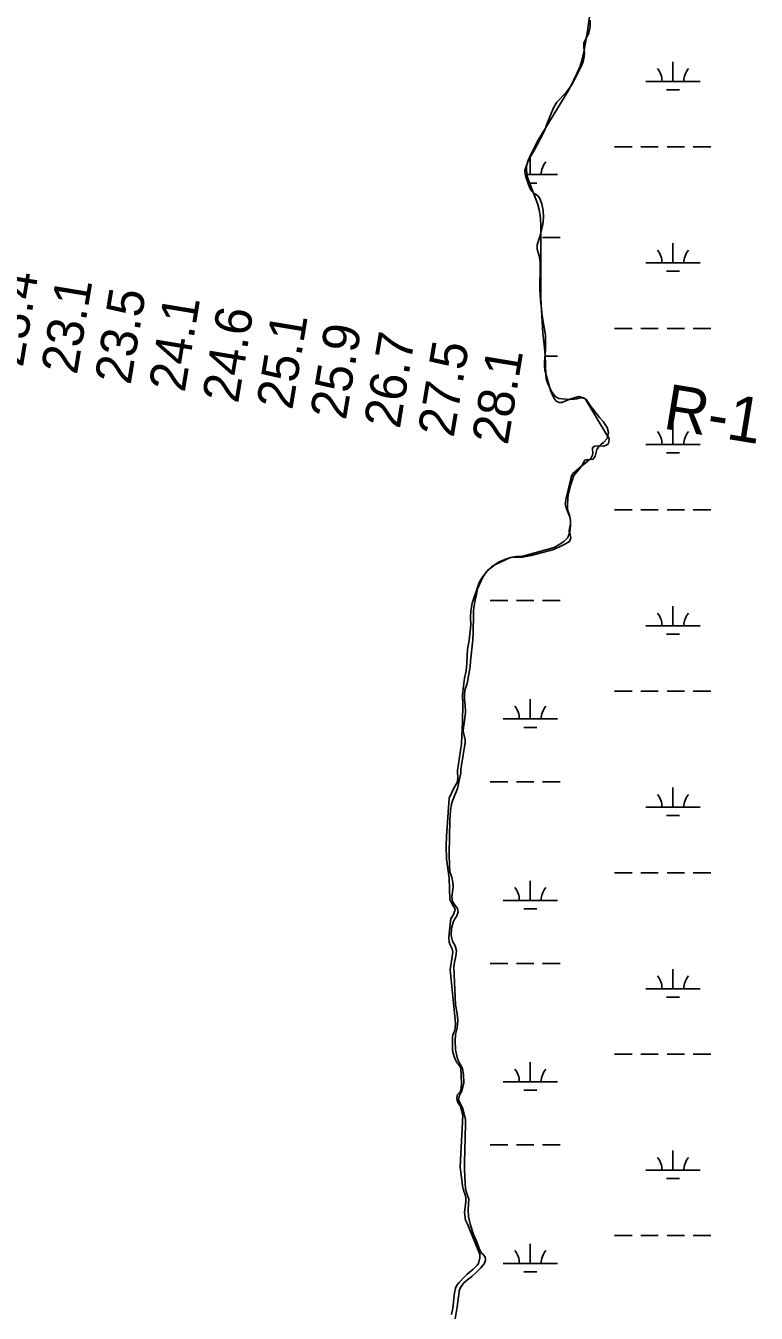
# Model space of a CAD drawing. Extents: x 3161564 to 3199464, y 849354 to 874788.
# Drawn here: x 3176471 to 3177810, y 868553 to 870914 of the extents above; entities that cross this region are included whole.
import ezdxf

# ---------------------------------------------------------------- set-up
doc = ezdxf.new("R2010")
doc.units = 0
for name, color, linetype in [('V-RIVR-RANG', 7, 'Continuous'), ('V-RIVR-RANG-IDEN', 7, 'Continuous'), ('V-SITE-VEGE', 7, 'Continuous'), ('V-TOPO-SHOR', 7, 'Continuous'), ('V-WETL-SWMP', 7, 'Continuous')]:
    doc.layers.add(name, color=color, linetype=linetype)

msp = doc.modelspace()

# ---------------------------------------------------------------- linework, layer by layer
at = {"layer": 'V-SITE-VEGE'}
for points in [[(3177505.5, 870924.1), (3177506, 870912.6), (3177503.4, 870901.1), (3177494.1, 870882.1), (3177494.2, 870873.9), (3177495.4, 870864.6), (3177494.9, 870856.7), (3177492.9, 870848.5), (3177490.2, 870842), (3177480.9, 870821.9), (3177477, 870815.1), (3177471.5, 870804.6), (3177461.8, 870791.5), (3177444.7, 870773.4), (3177438.7, 870763), (3177432.9, 870749.7), (3177427.6, 870736.7), (3177422, 870721), (3177408.7, 870695.2), (3177404.3, 870687.3), (3177397.4, 870675.8), (3177391.9, 870665.9), (3177385.7, 870648.7), (3177386.3, 870641.5), (3177388.2, 870634.8), (3177391.8, 870624.5), (3177395.3, 870616.2), (3177398.9, 870610.4), (3177403.3, 870606.4), (3177409.1, 870602.8), (3177412.8, 870598), (3177417.4, 870587.3), (3177419.8, 870575), (3177420.4, 870562.8), (3177419.8, 870554.3), (3177418.3, 870546.6), (3177413.3, 870527.7), (3177408.5, 870512), (3177408.4, 870504.2), (3177412.2, 870492.1), (3177413.8, 870481.2), (3177414.2, 870470.4), (3177414.1, 870458.3), (3177413.6, 870446.4), (3177413.2, 870429.8), (3177414.7, 870411.2), (3177417.9, 870381.7), (3177423.8, 870346.4), (3177424.1, 870331), (3177424, 870320.7), (3177422.2, 870296.5), (3177422, 870288.6), (3177422.6, 870282.4), (3177432.8, 870245.2), (3177435.8, 870237.6), (3177439.8, 870230.5), (3177443.7, 870225.6), (3177448.8, 870222.8), (3177454, 870223.1), (3177468.6, 870229), (3177478.2, 870232.5), (3177484.9, 870234), (3177493.3, 870231.8), (3177498.4, 870228.6), (3177503.3, 870221.1), (3177507.5, 870215), (3177522.8, 870195.7), (3177529.5, 870188.2), (3177536.8, 870177.4), (3177539.1, 870168), (3177537.1, 870157.2), (3177530.3, 870149.9), (3177525.6, 870146.4), (3177520.9, 870141.4), (3177517.9, 870136.7), (3177514.8, 870124.4), (3177511.4, 870119), (3177502, 870118.2), (3177498.5, 870118.2), (3177495.3, 870117), (3177493.4, 870112.5), (3177490.2, 870106.8)], [(3177490.2, 870106.8), (3177477.7, 870095.9), (3177473.7, 870092.7), (3177471.1, 870086.4), (3177470, 870083), (3177461.8, 870047.6), (3177460.1, 870037.4), (3177461.5, 870030.2), (3177467.9, 870014.9), (3177469.6, 870007.6), (3177469.4, 869999.8), (3177467.8, 869992.7), (3177467.2, 869986.3), (3177468.8, 869980.4), (3177470.1, 869974.2), (3177467.6, 869968.2), (3177460.8, 869963.8), (3177453.2, 869960.1), (3177439.2, 869953.8), (3177397.5, 869942.5), (3177382, 869939.7), (3177364.1, 869939.8), (3177357.9, 869938.3), (3177350.6, 869934.9), (3177341.3, 869930.1), (3177332.3, 869926.1), (3177324.9, 869921.7), (3177319.2, 869916.7), (3177313.7, 869910), (3177309.1, 869903.1), (3177299.4, 869881.5), (3177297.4, 869871.3), (3177294.7, 869860.6), (3177293, 869850.7), (3177292.1, 869841.5), (3177291.7, 869833), (3177292.2, 869822.8), (3177291.6, 869813.1), (3177291.2, 869802.2), (3177290.4, 869787.9), (3177286.3, 869748.6), (3177285.7, 869739.1), (3177284.7, 869731.8), (3177280.1, 869708.2), (3177276.3, 869695.5), (3177275.3, 869686.7), (3177275.4, 869677.7), (3177276.4, 869668.5), (3177277.2, 869655.6), (3177274.9, 869634.7), (3177273.5, 869627.5), (3177273.1, 869621.2), (3177274.1, 869614.8), (3177276.8, 869604.9), (3177276.7, 869599.5), (3177269.8, 869558.1), (3177268.9, 869550.2), (3177268.8, 869543.9), (3177262.4, 869515.2), (3177253.2, 869492.8), (3177251.4, 869486.4), (3177249.8, 869474.2), (3177248.6, 869457.4), (3177247.2, 869396.1), (3177247.9, 869373.2), (3177248.8, 869362.7), (3177252, 869353), (3177253.9, 869343.1), (3177254.7, 869335), (3177252.4, 869317), (3177253.5, 869308.4), (3177258.2, 869300.9), (3177262.4, 869295.3), (3177263.6, 869288.6), (3177260.6, 869280.8), (3177257.6, 869276.6), (3177254.4, 869270.4), (3177251.9, 869259.1), (3177250.8, 869245.9), (3177253.7, 869235.8), (3177258.6, 869227), (3177260.7, 869217.9), (3177259.7, 869208.3), (3177256.9, 869196.7), (3177255.6, 869188.5), (3177258.7, 869118.6), (3177262, 869103), (3177263.1, 869089.8), (3177261.9, 869076.7), (3177259.2, 869064.3), (3177258.1, 869052.8), (3177259, 869036.3), (3177262.6, 869020), (3177267.9, 869008.6), (3177271.7, 869002.1), (3177273.7, 868989.6), (3177274.1, 868975.9), (3177270.8, 868960.7), (3177266.4, 868953.4), (3177264.5, 868945), (3177267.3, 868937.9)], [(3177267.3, 868937.9), (3177272.2, 868928.5), (3177276.1, 868914), (3177277.4, 868907.9), (3177277.5, 868899.7), (3177275.7, 868829.1), (3177275.7, 868816.6), (3177277, 868781), (3177280.5, 868771.1), (3177283.1, 868762.6), (3177282.8, 868754.1), (3177282, 868743.4), (3177282.8, 868731), (3177285.6, 868716.9), (3177291.9, 868697.6), (3177297.2, 868685.2), (3177302.3, 868672.3), (3177306.1, 868664), (3177309.6, 868661), (3177313.1, 868656.7), (3177313.7, 868649.9), (3177311.4, 868644.1), (3177305, 868635.7), (3177297.1, 868628.2), (3177288.6, 868620.7), (3177281.7, 868615.4), (3177274.1, 868608.9), (3177267.8, 868600.5), (3177265.7, 868594.2), (3177265.4, 868592.6), (3177261.8, 868565.3), (3177258.6, 868543.1)]]:
    msp.add_lwpolyline(points, dxfattribs=at)
at = {"layer": 'V-TOPO-SHOR'}
for points in [[(3177505, 870934.6), (3177501.8, 870913), (3177500.9, 870903.8), (3177494.6, 870869.2), (3177491.1, 870852.3), (3177487.7, 870839.5), (3177482, 870827.5), (3177475, 870813.7), (3177466.6, 870796.1), (3177409.5, 870702.3), (3177394.7, 870672.7), (3177391.1, 870663.7), (3177389.3, 870655.8), (3177388.8, 870649.1), (3177390.2, 870638.3), (3177392.6, 870630.9), (3177409.2, 870587.9), (3177412.2, 870576), (3177414.5, 870562)], [(3177414.5, 870562), (3177415.4, 870546.6), (3177415.3, 870532.4), (3177415.1, 870413.9), (3177418.8, 870350.3), (3177421.4, 870329.4), (3177423.4, 870309.7), (3177424.3, 870273.6), (3177425.2, 870266.2), (3177427.8, 870259.3), (3177435.1, 870243.1), (3177441.6, 870234.2), (3177448.1, 870230.3), (3177454.4, 870229.5), (3177468.2, 870228.8), (3177476.6, 870229.1), (3177481.3, 870229.8), (3177487.5, 870231.4), (3177491.6, 870231.8), (3177495.5, 870230.4), (3177497.5, 870228), (3177536.8, 870162.5), (3177539.8, 870158.3), (3177540.7, 870155.3), (3177539.3, 870148.1), (3177535.7, 870144.7), (3177530.4, 870143.1), (3177520.1, 870143.9), (3177514, 870143.1), (3177509.9, 870140.3), (3177510.1, 870136.1), (3177510.6, 870131.3), (3177510.1, 870126.6), (3177507.6, 870121.7), (3177501.9, 870116), (3177494.8, 870110.1), (3177488.9, 870104.6), (3177475.9, 870089.1), (3177469.7, 870071.1), (3177465.7, 870054.7), (3177464, 870037.9), (3177464, 870028.7), (3177465.7, 870022.7), (3177467.9, 870016.8), (3177469.7, 870007.6), (3177469.9, 869997.7), (3177468.7, 869985.6), (3177464.6, 869975.6), (3177457.6, 869968.2), (3177450, 869963.2), (3177439.8, 869957.4), (3177382.1, 869941.4), (3177370.2, 869940.5), (3177360.3, 869938.9), (3177349.4, 869935.2), (3177340.4, 869931.3), (3177332.4, 869926.7), (3177322.6, 869918.8), (3177314.3, 869910.9), (3177308, 869902.2), (3177302.4, 869892.8), (3177289.7, 869855), (3177287.2, 869840.4), (3177286.7, 869829.5), (3177286.8, 869815.3), (3177283.9, 869787), (3177281.2, 869771), (3177279.8, 869745.4), (3177278.2, 869731.4), (3177275.7, 869717.9), (3177273.4, 869703), (3177271.9, 869687.2), (3177272.2, 869669.5), (3177271.7, 869638.5), (3177269.9, 869597), (3177262.7, 869548.1), (3177263.3, 869533.3), (3177261.8, 869526.6), (3177260.2, 869523.2), (3177255.7, 869516.1), (3177247.5, 869497.8)], [(3177268.5, 869003.1), (3177266.5, 869006.7), (3177260.9, 869014.5), (3177258.1, 869019.2), (3177256.3, 869024), (3177254.3, 869031.9), (3177253.4, 869036.5), (3177253.3, 869059.6), (3177253.8, 869063.5), (3177257, 869070.6), (3177258.5, 869075.9), (3177258.7, 869085), (3177249.3, 869182.9), (3177253.2, 869210.8), (3177254, 869215.6), (3177253.1, 869221.2), (3177251.5, 869223.9), (3177249.3, 869228.8), (3177247.5, 869233.6), (3177246.9, 869242.4), (3177249.8, 869273.1), (3177251.1, 869277.9), (3177254.4, 869283), (3177257.9, 869291.3), (3177258.3, 869294.2), (3177251.8, 869305.9), (3177248.8, 869312), (3177247.2, 869350.9), (3177242.2, 869386.4), (3177242, 869409.7), (3177242.6, 869427.4), (3177247.5, 869497.8)], [(3177251.9, 868551), (3177254.1, 868562.8), (3177257.1, 868590.9), (3177258.7, 868599.4), (3177261.4, 868605.1), (3177265.5, 868609.8), (3177275.3, 868620), (3177280.4, 868624.9), (3177290.4, 868633.6), (3177298.5, 868641.2), (3177301.2, 868644.7), (3177303.8, 868655.1), (3177303.4, 868661.1), (3177301.8, 868666), (3177280.7, 868716.5), (3177277.2, 868723.9), (3177275.7, 868738.2), (3177277.9, 868758.4), (3177277.7, 868765), (3177276, 868773.1), (3177274.1, 868776.3), (3177271.7, 868787.1), (3177267.3, 868821.6), (3177272.2, 868916.7), (3177268.3, 868932.5), (3177267.5, 868933.8), (3177264, 868938.3), (3177261.8, 868943.1), (3177261.2, 868948), (3177262.6, 868954.1), (3177268, 868960.3), (3177269.2, 868966.9), (3177270, 868974.5), (3177268.5, 869003.1)]]:
    msp.add_lwpolyline(points, dxfattribs=at)
at = {"layer": 'V-WETL-SWMP'}
for p, q in [((3177501.8, 870913), (3177505, 870934.6)), ((3177500.9, 870903.8), (3177501.8, 870913)), ((3177494.6, 870869.2), (3177500.9, 870903.8)), ((3177491.1, 870852.3), (3177494.6, 870869.2)), ((3177482, 870827.5), (3177487.7, 870839.5)), ((3177487.7, 870839.5), (3177491.1, 870852.3)), ((3177657.5, 870811.7), (3177657.5, 870847.7)), ((3177475, 870813.7), (3177482, 870827.5)), ((3177409.5, 870702.3), (3177466.6, 870796.1)), ((3177466.6, 870796.1), (3177475, 870813.7)), ((3177607.5, 870811.7), (3177707.5, 870811.7)), ((3177645.5, 870796.3), (3177669.5, 870796.3)), ((3177394.7, 870672.7), (3177409.5, 870702.3)), ((3177396, 870640.9), (3177396, 870675.5)), ((3177550.6, 870691.6), (3177582.6, 870691.6)), ((3177598.6, 870691.6), (3177630.6, 870691.6)), ((3177646.6, 870691.6), (3177678.6, 870691.6)), ((3177694.6, 870691.6), (3177726.6, 870691.6)), ((3177388.8, 870649.1), (3177389.3, 870655.8)), ((3177389.3, 870655.8), (3177391.1, 870663.7)), ((3177391.1, 870663.7), (3177394.7, 870672.7)), ((3177390.2, 870638.3), (3177388.8, 870649.1)), ((3177389.9, 870640.9), (3177446, 870640.9)), ((3177392.6, 870630.9), (3177390.2, 870638.3)), ((3177409.2, 870587.9), (3177392.6, 870630.9)), ((3177394.7, 870625.4), (3177408, 870625.4)), ((3177412.2, 870576), (3177409.2, 870587.9)), ((3177414.5, 870562), (3177412.2, 870576)), ((3177415.4, 870546.6), (3177414.5, 870562)), ((3177415.1, 870413.9), (3177415.3, 870532.4)), ((3177415.3, 870532.4), (3177415.4, 870546.6)), ((3177418.6, 870525.4), (3177450.6, 870525.4)), ((3177657.5, 870479), (3177657.5, 870515)), ((3177607.5, 870479), (3177707.5, 870479)), ((3177645.5, 870463.6), (3177669.5, 870463.6)), ((3177418.8, 870350.3), (3177415.1, 870413.9)), ((3177421.4, 870329.4), (3177418.8, 870350.3)), ((3177550.6, 870358.9), (3177582.6, 870358.9)), ((3177598.6, 870358.9), (3177630.6, 870358.9)), ((3177646.6, 870358.9), (3177678.6, 870358.9)), ((3177694.6, 870358.9), (3177726.6, 870358.9)), ((3177423.4, 870309.7), (3177421.4, 870329.4)), ((3177424.3, 870273.6), (3177423.4, 870309.7)), ((3177423.4, 870308.2), (3177446, 870308.2)), ((3177425.2, 870266.2), (3177424.3, 870273.6)), ((3177427.8, 870259.3), (3177425.2, 870266.2)), ((3177435.1, 870243.1), (3177427.8, 870259.3)), ((3177441.6, 870234.2), (3177435.1, 870243.1)), ((3177448.1, 870230.3), (3177441.6, 870234.2)), ((3177454.4, 870229.5), (3177448.1, 870230.3)), ((3177468.2, 870228.8), (3177454.4, 870229.5)), ((3177476.6, 870229.1), (3177468.2, 870228.8)), ((3177481.3, 870229.8), (3177476.6, 870229.1)), ((3177487.5, 870231.4), (3177481.3, 870229.8)), ((3177491.6, 870231.8), (3177487.5, 870231.4)), ((3177495.5, 870230.4), (3177491.6, 870231.8)), ((3177497.5, 870228), (3177495.5, 870230.4)), ((3177536.8, 870162.5), (3177497.5, 870228)), ((3177657.5, 870146.3), (3177657.5, 870182.3)), ((3177539.8, 870158.3), (3177536.8, 870162.5)), ((3177539.3, 870148.1), (3177540.7, 870155.3)), ((3177540.7, 870155.3), (3177539.8, 870158.3)), ((3177509.9, 870140.3), (3177514, 870143.1)), ((3177510.1, 870136.1), (3177509.9, 870140.3)), ((3177510.6, 870131.3), (3177510.1, 870136.1)), ((3177510.1, 870126.6), (3177510.6, 870131.3)), ((3177514, 870143.1), (3177520.1, 870143.9)), ((3177520.1, 870143.9), (3177530.4, 870143.1)), ((3177530.4, 870143.1), (3177535.7, 870144.7)), ((3177535.7, 870144.7), (3177539.3, 870148.1)), ((3177607.5, 870146.3), (3177707.5, 870146.3)), ((3177645.5, 870130.9), (3177669.5, 870130.9)), ((3177488.9, 870104.6), (3177494.8, 870110.1)), ((3177494.8, 870110.1), (3177501.9, 870116)), ((3177501.9, 870116), (3177507.6, 870121.7)), ((3177507.6, 870121.7), (3177510.1, 870126.6)), ((3177469.6, 870071.1), (3177475.9, 870089.1)), ((3177475.9, 870089.1), (3177488.9, 870104.6)), ((3177465.7, 870054.7), (3177469.6, 870071.1)), ((3177464, 870037.9), (3177465.7, 870054.7)), ((3177464, 870028.7), (3177464, 870037.9)), ((3177465.7, 870022.7), (3177464, 870028.7)), ((3177467.9, 870016.8), (3177465.7, 870022.7)), ((3177469.7, 870007.6), (3177467.9, 870016.8)), ((3177550.6, 870026.3), (3177582.6, 870026.3)), ((3177598.6, 870026.3), (3177630.6, 870026.3)), ((3177646.6, 870026.3), (3177678.6, 870026.3)), ((3177694.6, 870026.3), (3177726.6, 870026.3)), ((3177468.7, 869985.6), (3177469.9, 869997.7)), ((3177469.9, 869997.7), (3177469.7, 870007.6)), ((3177450, 869963.2), (3177457.6, 869968.2)), ((3177457.6, 869968.2), (3177464.6, 869975.6)), ((3177464.6, 869975.6), (3177468.7, 869985.6)), ((3177382.1, 869941.4), (3177439.8, 869957.4)), ((3177439.8, 869957.4), (3177450, 869963.2)), ((3177314.3, 869910.9), (3177322.6, 869918.8)), ((3177322.6, 869918.8), (3177332.4, 869926.7)), ((3177332.4, 869926.7), (3177340.4, 869931.3)), ((3177340.4, 869931.3), (3177349.4, 869935.2)), ((3177349.4, 869935.2), (3177360.3, 869938.9)), ((3177360.3, 869938.9), (3177370.2, 869940.5)), ((3177370.2, 869940.5), (3177382.1, 869941.4)), ((3177302.4, 869892.8), (3177308, 869902.2)), ((3177308, 869902.2), (3177314.3, 869910.9)), ((3177289.7, 869855), (3177302.4, 869892.8)), ((3177287.2, 869840.4), (3177289.7, 869855)), ((3177322.6, 869860.1), (3177354.6, 869860.1)), ((3177370.6, 869860.1), (3177402.6, 869860.1)), ((3177418.6, 869860.1), (3177450.6, 869860.1)), ((3177657.5, 869813.7), (3177657.5, 869849.7)), ((3177286.7, 869829.5), (3177287.2, 869840.4)), ((3177286.8, 869815.3), (3177286.7, 869829.5)), ((3177283.9, 869787), (3177286.8, 869815.3)), ((3177607.5, 869813.7), (3177707.5, 869813.7)), ((3177281.2, 869771), (3177283.9, 869787)), ((3177645.5, 869798.2), (3177669.5, 869798.2)), ((3177279.8, 869745.4), (3177281.2, 869771)), ((3177275.7, 869717.9), (3177278.2, 869731.4)), ((3177278.2, 869731.4), (3177279.8, 869745.4)), ((3177273.4, 869703), (3177275.7, 869717.9)), ((3177271.9, 869687.2), (3177273.4, 869703)), ((3177272.2, 869669.5), (3177271.9, 869687.2)), ((3177550.6, 869693.6), (3177582.6, 869693.6)), ((3177598.6, 869693.6), (3177630.6, 869693.6)), ((3177646.6, 869693.6), (3177678.6, 869693.6)), ((3177694.6, 869693.6), (3177726.6, 869693.6)), ((3177271.7, 869638.5), (3177272.2, 869669.5)), ((3177396, 869642.9), (3177396, 869678.9)), ((3177269.9, 869597), (3177271.7, 869638.5)), ((3177346, 869642.9), (3177446, 869642.9)), ((3177384, 869627.4), (3177408, 869627.4)), ((3177262.7, 869548.1), (3177269.9, 869597)), ((3177263.3, 869533.3), (3177262.7, 869548.1)), ((3177255.7, 869516.1), (3177260.2, 869523.2)), ((3177260.2, 869523.2), (3177261.8, 869526.6)), ((3177261.8, 869526.6), (3177263.3, 869533.3)), ((3177322.6, 869527.4), (3177354.6, 869527.4)), ((3177370.6, 869527.4), (3177402.6, 869527.4)), ((3177418.6, 869527.4), (3177450.6, 869527.4)), ((3177657.5, 869481), (3177657.5, 869517)), ((3177242.6, 869427.4), (3177247.5, 869497.8)), ((3177247.5, 869497.8), (3177255.7, 869516.1)), ((3177607.5, 869481), (3177707.5, 869481)), ((3177645.5, 869465.6), (3177669.5, 869465.6)), ((3177242, 869409.7), (3177242.6, 869427.4)), ((3177242.2, 869386.4), (3177242, 869409.7)), ((3177247.2, 869350.9), (3177242.2, 869386.4)), ((3177550.6, 869360.9), (3177582.6, 869360.9)), ((3177598.6, 869360.9), (3177630.6, 869360.9)), ((3177646.6, 869360.9), (3177678.6, 869360.9)), ((3177694.6, 869360.9), (3177726.6, 869360.9)), ((3177248.8, 869312), (3177247.2, 869350.9)), ((3177396, 869310.2), (3177396, 869346.2)), ((3177251.8, 869305.9), (3177248.8, 869312)), ((3177258.3, 869294.2), (3177251.8, 869305.9)), ((3177346, 869310.2), (3177446, 869310.2)), ((3177251.1, 869277.9), (3177254.4, 869283)), ((3177254.4, 869283), (3177257.9, 869291.3)), ((3177257.9, 869291.3), (3177258.3, 869294.2)), ((3177384, 869294.7), (3177408, 869294.7)), ((3177246.9, 869242.4), (3177249.8, 869273.1)), ((3177249.8, 869273.1), (3177251.1, 869277.9)), ((3177247.5, 869233.6), (3177246.9, 869242.4)), ((3177249.3, 869228.8), (3177247.5, 869233.6)), ((3177251.5, 869223.9), (3177249.3, 869228.8)), ((3177249.3, 869182.9), (3177253.2, 869210.8)), ((3177253.1, 869221.2), (3177251.5, 869223.9)), ((3177254, 869215.6), (3177253.1, 869221.2)), ((3177253.2, 869210.8), (3177254, 869215.6)), ((3177322.6, 869194.7), (3177354.6, 869194.7)), ((3177370.6, 869194.7), (3177402.6, 869194.7)), ((3177418.6, 869194.7), (3177450.6, 869194.7)), ((3177258.7, 869085), (3177249.3, 869182.9)), ((3177657.5, 869148.3), (3177657.5, 869184.3)), ((3177607.5, 869148.3), (3177707.5, 869148.3)), ((3177645.5, 869132.9), (3177669.5, 869132.9)), ((3177253.8, 869063.5), (3177257, 869070.6)), ((3177257, 869070.6), (3177258.5, 869075.9)), ((3177258.5, 869075.9), (3177258.7, 869085)), ((3177253.3, 869059.6), (3177253.8, 869063.5)), ((3177253.4, 869036.5), (3177253.3, 869059.6)), ((3177254.3, 869031.9), (3177253.4, 869036.5)), ((3177256.3, 869024), (3177254.3, 869031.9)), ((3177258.1, 869019.2), (3177256.3, 869024)), ((3177550.6, 869028.2), (3177582.6, 869028.2)), ((3177598.6, 869028.2), (3177630.6, 869028.2)), ((3177646.6, 869028.2), (3177678.6, 869028.2)), ((3177694.6, 869028.2), (3177726.6, 869028.2)), ((3177260.9, 869014.5), (3177258.1, 869019.2)), ((3177266.5, 869006.7), (3177260.9, 869014.5)), ((3177268.5, 869003.1), (3177266.5, 869006.7)), ((3177270, 868974.5), (3177268.5, 869003.1)), ((3177396, 868977.5), (3177396, 869013.5)), ((3177269.2, 868966.9), (3177270, 868974.5)), ((3177346, 868977.5), (3177446, 868977.5)), ((3177261.2, 868948), (3177262.6, 868954.1)), ((3177262.6, 868954.1), (3177268, 868960.3)), ((3177268, 868960.3), (3177269.2, 868966.9)), ((3177384, 868962.1), (3177408, 868962.1)), ((3177261.8, 868943.1), (3177261.2, 868948)), ((3177264, 868938.3), (3177261.8, 868943.1)), ((3177267.5, 868933.8), (3177264, 868938.3)), ((3177268.3, 868932.5), (3177267.5, 868933.8)), ((3177272.2, 868916.7), (3177268.3, 868932.5)), ((3177267.3, 868821.6), (3177272.2, 868916.7)), ((3177322.6, 868862.1), (3177354.6, 868862.1)), ((3177370.6, 868862.1), (3177402.6, 868862.1)), ((3177418.6, 868862.1), (3177450.6, 868862.1)), ((3177657.5, 868815.6), (3177657.5, 868851.6)), ((3177271.7, 868787.1), (3177267.3, 868821.6)), ((3177607.5, 868815.6), (3177707.5, 868815.6)), ((3177274.1, 868776.3), (3177271.7, 868787.1)), ((3177645.5, 868800.2), (3177669.5, 868800.2)), ((3177276, 868773.1), (3177274.1, 868776.3)), ((3177277.7, 868765), (3177276, 868773.1)), ((3177277.9, 868758.4), (3177277.7, 868765)), ((3177275.7, 868738.2), (3177277.9, 868758.4)), ((3177277.2, 868723.9), (3177275.7, 868738.2)), ((3177280.7, 868716.5), (3177277.2, 868723.9)), ((3177301.8, 868666), (3177280.7, 868716.5)), ((3177550.6, 868695.6), (3177582.6, 868695.6)), ((3177598.6, 868695.6), (3177630.6, 868695.6)), ((3177646.6, 868695.6), (3177678.6, 868695.6)), ((3177694.6, 868695.6), (3177726.6, 868695.6)), ((3177396, 868644.8), (3177396, 868680.8)), ((3177298.5, 868641.2), (3177301.2, 868644.7)), ((3177301.2, 868644.7), (3177303.8, 868655.1)), ((3177303.5, 868661.1), (3177301.8, 868666)), ((3177303.8, 868655.1), (3177303.5, 868661.1)), ((3177346, 868644.8), (3177446, 868644.8)), ((3177265.5, 868609.8), (3177275.3, 868620)), ((3177275.3, 868620), (3177280.5, 868624.9)), ((3177280.5, 868624.9), (3177290.4, 868633.6)), ((3177290.4, 868633.6), (3177298.5, 868641.2)), ((3177384, 868629.4), (3177408, 868629.4)), ((3177257.1, 868590.9), (3177258.7, 868599.4)), ((3177258.7, 868599.4), (3177261.4, 868605.1)), ((3177261.4, 868605.1), (3177265.5, 868609.8)), ((3177254.1, 868562.8), (3177257.1, 868590.9)), ((3177251.9, 868551), (3177254.1, 868562.8))]:
    msp.add_line(p, q, dxfattribs=at)
for centre, start, end in [((3177602.2, 870812.2), 359.2282, 40.7718), ((3177712.7, 870812.2), 139.2282, 180.7718), ((3177451.3, 870641.4), 139.2282, 180.7718), ((3177602.2, 870479.5), 359.2282, 40.7718), ((3177712.7, 870479.5), 139.2282, 180.7718), ((3177451.3, 870308.7), 139.2282, 147.5425), ((3177602.2, 870146.8), 359.2282, 40.7718), ((3177712.7, 870146.8), 139.2282, 180.7718), ((3177602.2, 869814.1), 359.2282, 40.7718), ((3177712.7, 869814.1), 139.2282, 180.7718), ((3177340.8, 869643.3), 359.2282, 40.7718), ((3177451.3, 869643.3), 139.2282, 180.7718), ((3177602.2, 869481.5), 359.2282, 40.7718), ((3177712.7, 869481.5), 139.2282, 180.7718), ((3177340.8, 869310.7), 359.2282, 40.7718), ((3177451.3, 869310.7), 139.2282, 180.7718), ((3177602.2, 869148.8), 359.2282, 40.7718), ((3177712.7, 869148.8), 139.2282, 180.7718), ((3177340.8, 868978), 359.2282, 40.7718), ((3177451.3, 868978), 139.2282, 180.7718), ((3177602.2, 868816.1), 359.2282, 40.7718), ((3177712.7, 868816.1), 139.2282, 180.7718), ((3177340.8, 868645.3), 359.2282, 40.7718), ((3177451.3, 868645.3), 139.2282, 180.7718)]:
    msp.add_arc(centre, 35.2, start, end, dxfattribs=at)

# ---------------------------------------------------------------- texts
at = {"layer": 'V-RIVR-RANG'}
for s, p in [('23.4', (3176465.9, 870286.3)), ('23.1', (3176565, 870272.5)), ('23.5', (3176663.3, 870254)), ('24.1', (3176762.4, 870240.2)), ('24.6', (3176860.4, 870219.9)), ('25.1', (3176959.7, 870208)), ('25.9', (3177058, 870189.3)), ('26.7', (3177156.7, 870173.4)), ('27.5', (3177255.4, 870157.3)), ('28.1', (3177354.5, 870143.5))]:
    msp.add_text(s, height=67, rotation=80.5783, dxfattribs=at).set_placement(p)
at = {"layer": 'V-RIVR-RANG-IDEN'}
msp.add_text('R-1', height=83, rotation=350.7196, dxfattribs=at).set_placement((3177637.5, 870175.7))

doc.saveas('drawing.dxf')
